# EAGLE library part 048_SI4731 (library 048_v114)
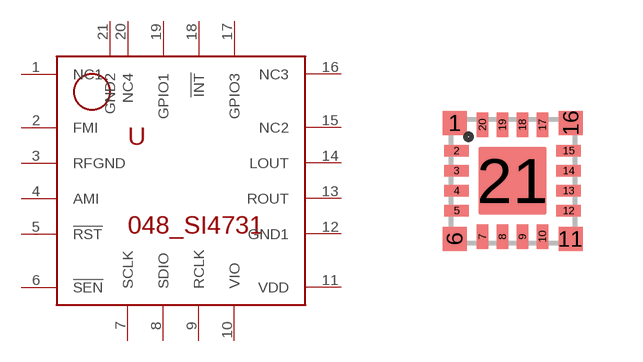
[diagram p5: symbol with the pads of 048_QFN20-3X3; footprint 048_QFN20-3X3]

Designator prefix -

## 048_SI4731  [048_QFN20-3X3]
1  NC1
2  FMI
3  RFGND  pwr
4  AMI
5  !RST
6  !SEN
7  SCLK
8  SDIO
9  RCLK
10  VIO  pwr
11  VDD  pwr
12  GND1  pwr
13  ROUT
14  LOUT
15  NC2
16  NC3
17  GPIO3
18  !INT
19  GPIO1
20  NC4
21  GND2  pwr

## Footprint 048_QFN20-3X3 (pad centres in mm)
smd 0.6 x 0.6: 1 -1.45,1.45; 6 -1.45,-1.45; 11 1.45,-1.45; 16 1.45,1.45
smd 0.61 x 0.28: 2 -1.4,0.75; 3 -1.4,0.25; 4 -1.4,-0.25; 5 -1.4,-0.75; 12 1.4,-0.75; 13 1.4,-0.25; 14 1.4,0.25; 15 1.4,0.75
smd 0.28 x 0.61: 7 -0.75,-1.4; 8 -0.25,-1.4; 9 0.25,-1.4; 10 0.75,-1.4; 17 0.75,1.4; 18 0.25,1.4; 19 -0.25,1.4; 20 -0.75,1.4
smd 1.7 x 1.7: 21 0,0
